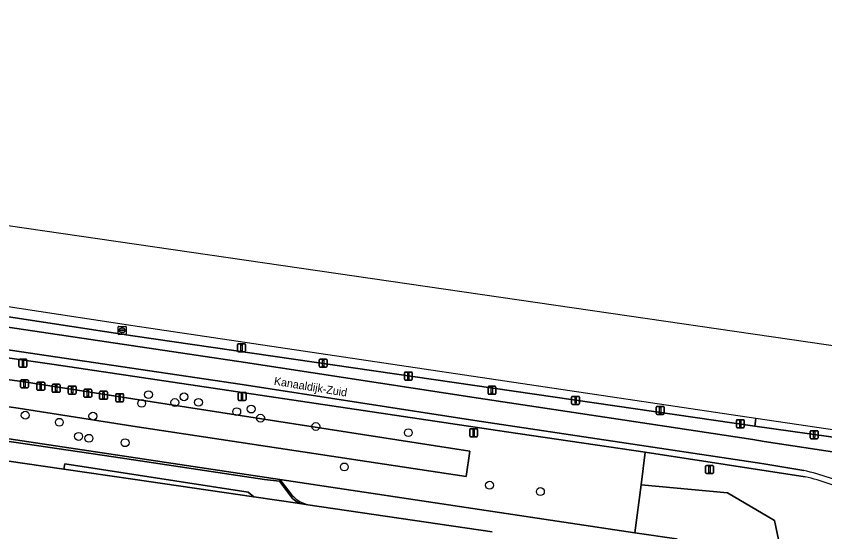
# Model space of a CAD drawing. Extents: x 163043 to 165076, y 382019 to 382874.
# Drawn here: x 164485.4 to 164586.4, y 382621.4 to 382685.8 of the extents above; entities that cross this region are included whole.
import ezdxf

# ---------------------------------------------------------------- set-up
doc = ezdxf.new("R2010")
doc.units = 0
for name, color, linetype in [('IMGEO_Afsluitpaal', 7, 'Continuous'), ('IMGEO_Boom', 7, 'Continuous'), ('IMGEO_Fietspad_gesloten', 7, 'Continuous'), ('IMGEO_Groenvoorziening', 7, 'Continuous'), ('IMGEO_Hek', 7, 'Continuous'), ('IMGEO_Lichtmast', 7, 'Continuous'), ('IMGEO_Loofbos', 7, 'Continuous'), ('IMGEO_Oever', 7, 'Continuous'), ('IMGEO_Openbare_ruimte_label', 7, 'Continuous'), ('IMGEO_Rijbaan_lokaal_gesloten', 7, 'Continuous'), ('IMGEO_Rijbaan_lokaal_halfverhard', 7, 'Continuous'), ('IMGEO_Rioolput', 7, 'Continuous'), ('IMGEO_Waterloop', 7, 'Continuous')]:
    doc.layers.add(name, color=color, linetype=linetype)

msp = doc.modelspace()

# ---------------------------------------------------------------- linework, layer by layer
at = {"layer": 'IMGEO_Afsluitpaal'}
for p, q in [((164513.06, 382643.99), (164513.06, 382644.79)), ((164513.06, 382644.79), (164513.06, 382643.99)), ((164513.16, 382644.89), (164513.95, 382644.89)), ((164513.95, 382644.89), (164513.16, 382644.89)), ((164514.05, 382644.79), (164514.05, 382643.99)), ((164514.05, 382643.99), (164514.05, 382644.79)), ((164513.95, 382643.89), (164513.16, 382643.89)), ((164513.16, 382643.89), (164513.95, 382643.89)), ((164523.25, 382642.07), (164523.25, 382642.87)), ((164523.25, 382642.87), (164523.25, 382642.07)), ((164523.35, 382642.97), (164524.14, 382642.97)), ((164524.14, 382642.97), (164523.35, 382642.97)), ((164524.24, 382642.87), (164524.24, 382642.07)), ((164524.24, 382642.07), (164524.24, 382642.87)), ((164524.14, 382641.97), (164523.35, 382641.97)), ((164523.35, 382641.97), (164524.14, 382641.97)), ((164533.89, 382640.45), (164533.89, 382641.25)), ((164533.89, 382641.25), (164533.89, 382640.45)), ((164533.99, 382641.35), (164534.78, 382641.35)), ((164534.78, 382641.35), (164533.99, 382641.35)), ((164534.88, 382641.25), (164534.88, 382640.45)), ((164534.88, 382640.45), (164534.88, 382641.25)), ((164485.96, 382639.49), (164485.96, 382640.29)), ((164485.96, 382640.29), (164485.96, 382639.49)), ((164486.06, 382640.39), (164486.85, 382640.39)), ((164486.85, 382640.39), (164486.06, 382640.39)), ((164486.95, 382640.29), (164486.95, 382639.49)), ((164486.95, 382639.49), (164486.95, 382640.29)), ((164534.78, 382640.35), (164533.99, 382640.35)), ((164533.99, 382640.35), (164534.78, 382640.35)), ((164486.85, 382639.39), (164486.06, 382639.39)), ((164486.06, 382639.39), (164486.85, 382639.39)), ((164487.99, 382639.19), (164487.99, 382639.99)), ((164487.99, 382639.99), (164487.99, 382639.19)), ((164488.09, 382640.09), (164488.88, 382640.09)), ((164488.88, 382640.09), (164488.09, 382640.09)), ((164488.88, 382639.09), (164488.09, 382639.09)), ((164488.09, 382639.09), (164488.88, 382639.09)), ((164488.98, 382639.99), (164488.98, 382639.19)), ((164488.98, 382639.19), (164488.98, 382639.99)), ((164489.91, 382638.93), (164489.91, 382639.73)), ((164489.91, 382639.73), (164489.91, 382638.93)), ((164490.01, 382639.83), (164490.8, 382639.83)), ((164490.8, 382639.83), (164490.01, 382639.83)), ((164490.9, 382639.73), (164490.9, 382638.93)), ((164490.9, 382638.93), (164490.9, 382639.73)), ((164491.91, 382638.71), (164491.91, 382639.51)), ((164491.91, 382639.51), (164491.91, 382638.71)), ((164492.01, 382639.61), (164492.8, 382639.61)), ((164492.8, 382639.61), (164492.01, 382639.61)), ((164492.9, 382639.51), (164492.9, 382638.71)), ((164492.9, 382638.71), (164492.9, 382639.51)), ((164493.86, 382638.31), (164493.86, 382639.11)), ((164493.86, 382639.11), (164493.86, 382638.31)), ((164493.96, 382639.21), (164494.75, 382639.21)), ((164494.75, 382639.21), (164493.96, 382639.21)), ((164494.85, 382639.11), (164494.85, 382638.31)), ((164494.85, 382638.31), (164494.85, 382639.11)), ((164544.34, 382638.68), (164544.34, 382639.48)), ((164544.34, 382639.48), (164544.34, 382638.68)), ((164544.44, 382639.58), (164545.22, 382639.58)), ((164545.22, 382639.58), (164544.44, 382639.58)), ((164545.32, 382639.48), (164545.32, 382638.68)), ((164545.32, 382638.68), (164545.32, 382639.48)), ((164490.8, 382638.83), (164490.01, 382638.83)), ((164490.01, 382638.83), (164490.8, 382638.83)), ((164492.8, 382638.61), (164492.01, 382638.61)), ((164492.01, 382638.61), (164492.8, 382638.61)), ((164494.75, 382638.21), (164493.96, 382638.21)), ((164493.96, 382638.21), (164494.75, 382638.21)), ((164495.82, 382638.05), (164495.82, 382638.85)), ((164495.82, 382638.85), (164495.82, 382638.05)), ((164495.92, 382638.95), (164496.71, 382638.95)), ((164496.71, 382638.95), (164495.92, 382638.95)), ((164496.81, 382638.85), (164496.81, 382638.05)), ((164496.81, 382638.05), (164496.81, 382638.85)), ((164497.85, 382637.75), (164497.85, 382638.55)), ((164497.85, 382638.55), (164497.85, 382637.75)), ((164497.95, 382638.65), (164498.74, 382638.65)), ((164498.74, 382638.65), (164497.95, 382638.65)), ((164498.84, 382638.55), (164498.84, 382637.75)), ((164498.84, 382637.75), (164498.84, 382638.55)), ((164545.22, 382638.58), (164544.44, 382638.58)), ((164544.44, 382638.58), (164545.22, 382638.58)), ((164554.78, 382637.42), (164554.78, 382638.22)), ((164554.78, 382638.22), (164554.78, 382637.42)), ((164554.88, 382638.32), (164555.67, 382638.32)), ((164555.67, 382638.32), (164554.88, 382638.32)), ((164555.77, 382638.22), (164555.77, 382637.42)), ((164555.77, 382637.42), (164555.77, 382638.22)), ((164496.71, 382637.95), (164495.92, 382637.95)), ((164495.92, 382637.95), (164496.71, 382637.95)), ((164498.74, 382637.65), (164497.95, 382637.65)), ((164497.95, 382637.65), (164498.74, 382637.65)), ((164555.67, 382637.32), (164554.88, 382637.32)), ((164554.88, 382637.32), (164555.67, 382637.32)), ((164565.34, 382636.17), (164565.34, 382636.96)), ((164565.34, 382636.96), (164565.34, 382636.17)), ((164565.44, 382637.06), (164566.23, 382637.06)), ((164566.23, 382637.06), (164565.44, 382637.06)), ((164566.23, 382636.07), (164565.44, 382636.07)), ((164565.44, 382636.07), (164566.23, 382636.07)), ((164566.33, 382636.96), (164566.33, 382636.17)), ((164566.33, 382636.17), (164566.33, 382636.96)), ((164575.35, 382634.5), (164575.35, 382635.3)), ((164575.35, 382635.3), (164575.35, 382634.5)), ((164575.45, 382635.4), (164576.24, 382635.4)), ((164576.24, 382635.4), (164575.45, 382635.4)), ((164576.34, 382635.3), (164576.34, 382634.5)), ((164576.34, 382634.5), (164576.34, 382635.3)), ((164576.24, 382634.4), (164575.45, 382634.4)), ((164575.45, 382634.4), (164576.24, 382634.4)), ((164584.56, 382633.13), (164584.56, 382633.93)), ((164584.56, 382633.93), (164584.56, 382633.13)), ((164584.66, 382634.03), (164585.45, 382634.03)), ((164585.45, 382634.03), (164584.66, 382634.03)), ((164585.45, 382633.03), (164584.66, 382633.03)), ((164584.66, 382633.03), (164585.45, 382633.03)), ((164585.55, 382633.93), (164585.55, 382633.13)), ((164585.55, 382633.13), (164585.55, 382633.93))]:
    msp.add_line(p, q, dxfattribs=at)
for points in [[(164513.48, 382644.77), (164513.63, 382644.77), (164513.63, 382644.02), (164513.48, 382644.02), (164513.48, 382644.77)], [(164523.67, 382642.85), (164523.82, 382642.85), (164523.82, 382642.1), (164523.67, 382642.1), (164523.67, 382642.85)], [(164534.31, 382641.22), (164534.46, 382641.22), (164534.46, 382640.47), (164534.31, 382640.47), (164534.31, 382641.22)], [(164486.38, 382640.26), (164486.53, 382640.26), (164486.53, 382639.51), (164486.38, 382639.51), (164486.38, 382640.26)], [(164488.41, 382639.97), (164488.56, 382639.97), (164488.56, 382639.22), (164488.41, 382639.22), (164488.41, 382639.97)], [(164490.33, 382639.71), (164490.48, 382639.71), (164490.48, 382638.96), (164490.33, 382638.96), (164490.33, 382639.71)], [(164492.33, 382639.49), (164492.48, 382639.49), (164492.48, 382638.74), (164492.33, 382638.74), (164492.33, 382639.49)], [(164544.75, 382639.45), (164544.9, 382639.45), (164544.9, 382638.7), (164544.75, 382638.7), (164544.75, 382639.45)], [(164494.28, 382639.08), (164494.43, 382639.08), (164494.43, 382638.33), (164494.28, 382638.33), (164494.28, 382639.08)], [(164496.24, 382638.82), (164496.39, 382638.82), (164496.39, 382638.07), (164496.24, 382638.07), (164496.24, 382638.82)], [(164498.27, 382638.53), (164498.42, 382638.53), (164498.42, 382637.78), (164498.27, 382637.78), (164498.27, 382638.53)], [(164555.2, 382638.2), (164555.35, 382638.2), (164555.35, 382637.45), (164555.2, 382637.45), (164555.2, 382638.2)], [(164565.76, 382636.94), (164565.91, 382636.94), (164565.91, 382636.19), (164565.76, 382636.19), (164565.76, 382636.94)], [(164575.77, 382635.28), (164575.92, 382635.28), (164575.92, 382634.53), (164575.77, 382634.53), (164575.77, 382635.28)], [(164584.98, 382633.91), (164585.13, 382633.91), (164585.13, 382633.16), (164584.98, 382633.16), (164584.98, 382633.91)]]:
    msp.add_lwpolyline(points, dxfattribs=at)
for centre, start, end in [((164513.16, 382644.79), 90, 180), ((164513.16, 382644.79), 90, 180), ((164513.95, 382644.79), 0, 90), ((164513.95, 382644.79), 360, 90), ((164513.16, 382643.99), 180, 270), ((164513.16, 382643.99), 180, 270), ((164513.95, 382643.99), 270, 0), ((164513.95, 382643.99), 270, 0), ((164523.35, 382642.87), 90, 180), ((164523.35, 382642.87), 90, 180), ((164524.14, 382642.87), 0, 90), ((164524.14, 382642.87), 360, 90), ((164523.35, 382642.07), 180, 270), ((164523.35, 382642.07), 180, 270), ((164524.14, 382642.07), 270, 0), ((164524.14, 382642.07), 270, 0), ((164533.99, 382641.25), 90, 180), ((164533.99, 382641.25), 90, 180), ((164534.78, 382641.25), 0, 90), ((164534.78, 382641.25), 360, 90), ((164486.06, 382640.29), 90, 180), ((164486.06, 382640.29), 90, 180), ((164486.85, 382640.29), 0, 90), ((164486.85, 382640.29), 360, 90), ((164533.99, 382640.45), 180, 270), ((164533.99, 382640.45), 180, 270), ((164534.78, 382640.45), 270, 0), ((164534.78, 382640.45), 270, 0), ((164486.06, 382639.49), 180, 270), ((164486.06, 382639.49), 180, 270), ((164486.85, 382639.49), 270, 0), ((164486.85, 382639.49), 270, 0), ((164488.09, 382639.99), 90, 180), ((164488.09, 382639.99), 90, 180), ((164488.09, 382639.19), 180, 270), ((164488.09, 382639.19), 180, 270), ((164488.88, 382639.99), 0, 90), ((164488.88, 382639.99), 360, 90), ((164488.88, 382639.19), 270, 0), ((164488.88, 382639.19), 270, 0), ((164490.01, 382639.73), 90, 180), ((164490.01, 382639.73), 90, 180), ((164490.8, 382639.73), 0, 90), ((164490.8, 382639.73), 360, 90), ((164492.01, 382639.51), 90, 180), ((164492.01, 382639.51), 90, 180), ((164492.8, 382639.51), 0, 90), ((164492.8, 382639.51), 360, 90), ((164493.96, 382639.11), 90, 180), ((164493.96, 382639.11), 90, 180), ((164494.75, 382639.11), 0, 90), ((164494.75, 382639.11), 360, 90), ((164544.44, 382639.48), 90, 180), ((164544.44, 382639.48), 90, 180), ((164545.22, 382639.48), 0, 90), ((164545.22, 382639.48), 360, 90), ((164490.01, 382638.93), 180, 270), ((164490.01, 382638.93), 180, 270), ((164490.8, 382638.93), 270, 0), ((164490.8, 382638.93), 270, 0), ((164492.01, 382638.71), 180, 270), ((164492.01, 382638.71), 180, 270), ((164492.8, 382638.71), 270, 0), ((164492.8, 382638.71), 270, 0), ((164493.96, 382638.31), 180, 270), ((164493.96, 382638.31), 180, 270), ((164494.75, 382638.31), 270, 0), ((164494.75, 382638.31), 270, 0), ((164495.92, 382638.85), 90, 180), ((164495.92, 382638.85), 90, 180), ((164496.71, 382638.85), 0, 90), ((164496.71, 382638.85), 360, 90), ((164497.95, 382638.55), 90, 180), ((164497.95, 382638.55), 90, 180), ((164498.74, 382638.55), 0, 90), ((164498.74, 382638.55), 360, 90), ((164544.44, 382638.68), 180, 270), ((164544.44, 382638.68), 180, 270), ((164545.22, 382638.68), 270, 0), ((164545.22, 382638.68), 270, 0), ((164554.88, 382638.22), 90, 180), ((164554.88, 382638.22), 90, 180), ((164555.67, 382638.22), 0, 90), ((164555.67, 382638.22), 360, 90), ((164495.92, 382638.05), 180, 270), ((164495.92, 382638.05), 180, 270), ((164496.71, 382638.05), 270, 0), ((164496.71, 382638.05), 270, 0), ((164497.95, 382637.75), 180, 270), ((164497.95, 382637.75), 180, 270), ((164498.74, 382637.75), 270, 0), ((164498.74, 382637.75), 270, 0), ((164554.88, 382637.42), 180, 270), ((164554.88, 382637.42), 180, 270), ((164555.67, 382637.42), 270, 0), ((164555.67, 382637.42), 270, 0), ((164565.44, 382636.96), 90, 180), ((164565.44, 382636.96), 90, 180), ((164565.44, 382636.17), 180, 270), ((164565.44, 382636.17), 180, 270), ((164566.23, 382636.96), 0, 90), ((164566.23, 382636.96), 360, 90), ((164566.23, 382636.17), 270, 0), ((164566.23, 382636.17), 270, 0), ((164575.45, 382635.3), 90, 180), ((164575.45, 382635.3), 90, 180), ((164576.24, 382635.3), 0, 90), ((164576.24, 382635.3), 360, 90), ((164575.45, 382634.5), 180, 270), ((164575.45, 382634.5), 180, 270), ((164576.24, 382634.5), 270, 0), ((164576.24, 382634.5), 270, 0), ((164584.66, 382633.93), 90, 180), ((164584.66, 382633.93), 90, 180), ((164584.66, 382633.13), 180, 270), ((164584.66, 382633.13), 180, 270), ((164585.45, 382633.93), 0, 90), ((164585.45, 382633.93), 360, 90), ((164585.45, 382633.13), 270, 0), ((164585.45, 382633.13), 270, 0)]:
    msp.add_arc(centre, 0.1, start, end, dxfattribs=at)
at = {"layer": 'IMGEO_Boom'}
for centre in [(164501.95, 382638.53), (164506.38, 382638.26), (164501.09, 382637.44), (164505.23, 382637.55), (164508.19, 382637.57), (164514.77, 382636.73), (164486.55, 382635.96), (164495, 382635.84), (164512.96, 382636.4), (164515.93, 382635.6), (164490.81, 382635.08), (164522.84, 382634.55), (164534.39, 382633.78), (164493.21, 382633.31), (164494.5, 382633.08), (164499.02, 382632.52), (164526.39, 382629.5), (164544.53, 382627.21), (164550.88, 382626.42)]:
    msp.add_circle(centre, 0.489, dxfattribs=at)
at = {"layer": 'IMGEO_Fietspad_gesloten'}
for points in [[(164590.1, 382630.98), (164578.83, 382632.68), (164577.4, 382632.94), (164564.45, 382634.88), (164543.13, 382638.08), (164514.06, 382642.55), (164454.95, 382651.33), (164396.3, 382660.19), (164284.35, 382677.28), (164278.14, 382678.22), (164235.35, 382684.54)], [(164283.96, 382674.5), (164395.88, 382657.42), (164454.54, 382648.56), (164513.64, 382639.78), (164542.71, 382635.32), (164564.09, 382632.1), (164578.55, 382629.91), (164583.76, 382629.04)], [(164290.79, 382659.6), (164472.55, 382632.41), (164472.49, 382631.88), (164484.23, 382630.28), (164491.39, 382629.23), (164491.49, 382629.87), (164514.38, 382626.36), (164515.1, 382625.77), (164520.86, 382624.93), (164520.36, 382625.22), (164519.94, 382625.56), (164518.31, 382627.71), (164516.44, 382627.92), (164497.58, 382630.74), (164458.77, 382636.45), (164437.76, 382639.63), (164406.03, 382644.41), (164348.55, 382652.85), (164290.62, 382661.73)]]:
    msp.add_lwpolyline(points, dxfattribs=at)
msp.add_arc((164577.89, 382602.23), 27.45, 63.6861, 77.6519, dxfattribs=at)
at = {"layer": 'IMGEO_Groenvoorziening'}
for points in [[(164619.1, 382628.48), (164619.49, 382628.72), (164577.64, 382634.59), (164500, 382645.86), (164326.61, 382672.42), (164284.55, 382678.7), (164223.39, 382687.83), (164004.16, 382721.06), (164000, 382721.52), (163996.62, 382722), (163984.14, 382724.05), (163984.26, 382724.67), (163957.08, 382728.48), (163893.44, 382737.78)], [(164284.35, 382677.28), (164396.3, 382660.19), (164454.95, 382651.33), (164514.06, 382642.55), (164543.13, 382638.08), (164564.45, 382634.88), (164577.4, 382632.94), (164578.83, 382632.68), (164590.1, 382630.98)], [(164282.56, 382663.33), (164518.36, 382627.93), (164562.67, 382621.28), (164563.46, 382627.27), (164563.98, 382631.34), (164546.63, 382633.89), (164490.17, 382642.3), (164454.45, 382647.37), (164396.2, 382656.23), (164325.74, 382667.17)], [(164519.63, 382626.25), (164518.36, 382627.93), (164282.56, 382663.33)], [(164290.62, 382661.73), (164348.55, 382652.85), (164406.03, 382644.41), (164437.76, 382639.63), (164458.77, 382636.45), (164497.58, 382630.74), (164516.44, 382627.92), (164518.31, 382627.71), (164519.94, 382625.56), (164520.36, 382625.22), (164520.86, 382624.93), (164521.84, 382624.78)], [(164583.94, 382628.28), (164563.98, 382631.34), (164563.46, 382627.27), (164574.24, 382626.25), (164580.11, 382622.82), (164581.1, 382618.05), (164578.56, 382613.96), (164573.96, 382611.95), (164640.91, 382517.91), (164661.85, 382488.63), (164685.89, 382499.46), (164694.96, 382503.59), (164744.78, 382526.26), (164740.74, 382535.71)], [(164688.62, 382460.91), (164694.96, 382503.59), (164685.89, 382499.46), (164661.85, 382488.63), (164640.91, 382517.91), (164573.96, 382611.95), (164567.87, 382620.5), (164562.67, 382621.28), (164518.36, 382627.93), (164519.63, 382626.25)], [(164521.84, 382624.78), (164544.84, 382621.39)]]:
    msp.add_lwpolyline(points, dxfattribs=at)
for points in [[(164229.4, 382676.95), (164337.68, 382660.69), (164416.83, 382649.81), (164431.81, 382647.48), (164450.46, 382644.94), (164486.15, 382640.16), (164500, 382638.01), (164542.07, 382631.47), (164541.63, 382628.3), (164500, 382634.6), (164485.67, 382636.85), (164404.8, 382648.54), (164314.83, 382661.08), (164228.97, 382674.04)], [(164491.39, 382629.23), (164500, 382627.97), (164515.1, 382625.77), (164514.38, 382626.36), (164491.49, 382629.87)]]:
    msp.add_lwpolyline(points, close=True, dxfattribs=at)
for centre, radius, start, end in [((164576.73, 382597.84), 31.28, 65.2088, 76.6616), ((164522.82, 382628.66), 4, 217.0042, 255.7236), ((164522.82, 382628.66), 4, 217.0042, 255.7236)]:
    msp.add_arc(centre, radius, start, end, dxfattribs=at)
at = {"layer": 'IMGEO_Hek'}
for points in [[(164518.36, 382627.93), (164282.56, 382663.33)], [(164562.67, 382621.28), (164518.36, 382627.93)]]:
    msp.add_lwpolyline(points, dxfattribs=at)
at = {"layer": 'IMGEO_Lichtmast'}
for p, q in [((164485.77, 382642.07), (164485.77, 382642.87)), ((164485.77, 382642.87), (164485.77, 382642.07)), ((164485.87, 382642.97), (164486.66, 382642.97)), ((164486.66, 382642.97), (164485.87, 382642.97)), ((164486.76, 382642.87), (164486.76, 382642.07)), ((164486.76, 382642.07), (164486.76, 382642.87)), ((164486.66, 382641.97), (164485.87, 382641.97)), ((164485.87, 382641.97), (164486.66, 382641.97)), ((164513.13, 382637.91), (164513.13, 382638.71)), ((164513.13, 382638.71), (164513.13, 382637.91)), ((164513.23, 382638.81), (164514.02, 382638.81)), ((164514.02, 382638.81), (164513.23, 382638.81)), ((164514.12, 382638.71), (164514.12, 382637.91)), ((164514.12, 382637.91), (164514.12, 382638.71)), ((164514.02, 382637.81), (164513.23, 382637.81)), ((164513.23, 382637.81), (164514.02, 382637.81)), ((164542.05, 382633.37), (164542.05, 382634.17)), ((164542.05, 382634.17), (164542.05, 382633.37)), ((164542.15, 382634.27), (164542.94, 382634.27)), ((164542.94, 382634.27), (164542.15, 382634.27)), ((164543.04, 382634.17), (164543.04, 382633.37)), ((164543.04, 382633.37), (164543.04, 382634.17)), ((164542.94, 382633.27), (164542.15, 382633.27)), ((164542.15, 382633.27), (164542.94, 382633.27)), ((164571.51, 382628.78), (164571.51, 382629.58)), ((164571.51, 382629.58), (164571.51, 382628.78)), ((164571.61, 382629.68), (164572.4, 382629.68)), ((164572.4, 382629.68), (164571.61, 382629.68)), ((164572.5, 382629.58), (164572.5, 382628.78)), ((164572.5, 382628.78), (164572.5, 382629.58)), ((164572.4, 382628.68), (164571.61, 382628.68)), ((164571.61, 382628.68), (164572.4, 382628.68))]:
    msp.add_line(p, q, dxfattribs=at)
for points in [[(164486.19, 382642.85), (164486.34, 382642.85), (164486.34, 382642.1), (164486.19, 382642.1), (164486.19, 382642.85)], [(164513.55, 382638.68), (164513.7, 382638.68), (164513.7, 382637.93), (164513.55, 382637.93), (164513.55, 382638.68)], [(164542.47, 382634.15), (164542.62, 382634.15), (164542.62, 382633.4), (164542.47, 382633.4), (164542.47, 382634.15)], [(164571.93, 382629.56), (164572.08, 382629.56), (164572.08, 382628.81), (164571.93, 382628.81), (164571.93, 382629.56)]]:
    msp.add_lwpolyline(points, dxfattribs=at)
for centre, start, end in [((164485.87, 382642.87), 90, 180), ((164485.87, 382642.87), 90, 180), ((164486.66, 382642.87), 0, 90), ((164486.66, 382642.87), 360, 90), ((164485.87, 382642.07), 180, 270), ((164485.87, 382642.07), 180, 270), ((164486.66, 382642.07), 270, 0), ((164486.66, 382642.07), 270, 0), ((164513.23, 382638.71), 90, 180), ((164513.23, 382638.71), 90, 180), ((164514.02, 382638.71), 0, 90), ((164514.02, 382638.71), 360, 90), ((164513.23, 382637.91), 180, 270), ((164513.23, 382637.91), 180, 270), ((164514.02, 382637.91), 270, 0), ((164514.02, 382637.91), 270, 0), ((164542.15, 382634.17), 90, 180), ((164542.15, 382634.17), 90, 180), ((164542.94, 382634.17), 0, 90), ((164542.94, 382634.17), 360, 90), ((164542.15, 382633.37), 180, 270), ((164542.15, 382633.37), 180, 270), ((164542.94, 382633.37), 270, 0), ((164542.94, 382633.37), 270, 0), ((164571.61, 382629.58), 90, 180), ((164571.61, 382629.58), 90, 180), ((164572.4, 382629.58), 0, 90), ((164572.4, 382629.58), 360, 90), ((164571.61, 382628.78), 180, 270), ((164571.61, 382628.78), 180, 270), ((164572.4, 382628.78), 270, 0), ((164572.4, 382628.78), 270, 0)]:
    msp.add_arc(centre, 0.1, start, end, dxfattribs=at)
at = {"layer": 'IMGEO_Loofbos'}
msp.add_lwpolyline([(164573.96, 382611.95), (164578.56, 382613.96), (164581.1, 382618.05), (164580.11, 382622.82), (164574.24, 382626.25), (164563.46, 382627.27), (164562.67, 382621.28), (164567.87, 382620.5)], close=True, dxfattribs=at)
at = {"layer": 'IMGEO_Oever'}
for points in [[(164390.46, 382663.82), (164301.17, 382677.11), (164284.68, 382679.59), (164284.55, 382678.7), (164326.61, 382672.42), (164500, 382645.86), (164577.64, 382634.59), (164577.79, 382635.57), (164500, 382647.13)], [(164577.79, 382635.57), (164577.64, 382634.59), (164619.49, 382628.72), (164620.09, 382628.61), (164620.89, 382628.51), (164623.42, 382628.16), (164624.27, 382628.05), (164626.88, 382627.58), (164633.2, 382626.7), (164633.68, 382626.68), (164634.83, 382626.12), (164634.2, 382626.66), (164633.6, 382627.18), (164629.53, 382628.14), (164625.1, 382628.81), (164610.23, 382630.74)]]:
    msp.add_lwpolyline(points, close=True, dxfattribs=at)
at = {"layer": 'IMGEO_Rijbaan_lokaal_gesloten'}
msp.add_lwpolyline([(164544.84, 382621.39), (164521.84, 382624.78), (164520.86, 382624.93), (164515.1, 382625.77), (164500, 382627.97), (164491.39, 382629.23), (164484.23, 382630.28), (164472.49, 382631.88), (164467.18, 382632.47), (164458.53, 382633.3), (164451.73, 382634.17), (164290.57, 382658.01)], dxfattribs=at)
at = {"layer": 'IMGEO_Rijbaan_lokaal_halfverhard'}
for points in [[(164583.76, 382629.04), (164578.55, 382629.91), (164564.09, 382632.1), (164542.71, 382635.32), (164513.64, 382639.78), (164454.54, 382648.56), (164395.88, 382657.42), (164283.96, 382674.5), (164277.72, 382675.46), (164234.94, 382681.77), (164226.11, 382682.88), (164210.1, 382685.24), (164199.47, 382687.05), (164086.12, 382704.22), (163983.27, 382719.37), (163935.2, 382726.45), (163865.22, 382736.76), (163777.02, 382749.58)], [(164325.74, 382667.17), (164396.2, 382656.23), (164454.45, 382647.37), (164490.17, 382642.3), (164546.63, 382633.89), (164563.98, 382631.34), (164583.94, 382628.28)]]:
    msp.add_lwpolyline(points, dxfattribs=at)
for centre, radius, start, end in [((164577.89, 382602.23), 27.45, 63.6861, 77.6519), ((164576.73, 382597.84), 31.28, 65.2088, 76.6616)]:
    msp.add_arc(centre, radius, start, end, dxfattribs=at)
at = {"layer": 'IMGEO_Rioolput'}
for p, q in [((164498.15, 382646.14), (164498.15, 382646.99)), ((164498.22, 382647.06), (164499.07, 382647.06)), ((164498.4, 382646.56), (164498.4, 382646.57)), ((164498.84, 382646.52), (164498.44, 382646.52)), ((164498.45, 382646.61), (164498.84, 382646.61)), ((164498.63, 382646.84), (164498.66, 382646.84)), ((164498.66, 382646.28), (164498.63, 382646.28)), ((164498.89, 382646.57), (164498.89, 382646.56)), ((164499.15, 382646.99), (164499.15, 382646.14)), ((164499.07, 382646.06), (164498.22, 382646.06))]:
    msp.add_line(p, q, dxfattribs=at)
for points in [[(164498.15, 382646.14), (164498.15, 382646.99)], [(164498.22, 382647.06), (164499.07, 382647.06)], [(164499.15, 382646.99), (164499.15, 382646.14)], [(164499.07, 382646.06), (164498.22, 382646.06)]]:
    msp.add_lwpolyline(points, dxfattribs=at)
for centre, radius, start, end in [((164498.22, 382646.99), 0.0765, 91.552, 178.448), ((164498.22, 382646.99), 0.0765, 91.552, 178.448), ((164498.44, 382646.57), 0.0403, 85.8775, 175.7526), ((164498.44, 382646.56), 0.0366, 178.938, 274.7102), ((164498.85, 382646.57), 0.0386, 1.7309, 96.639), ((164498.85, 382646.56), 0.043, 264.8664, 352.4533), ((164499.07, 382646.99), 0.0765, 1.552, 88.448), ((164499.07, 382646.99), 0.0765, 1.552, 88.448), ((164498.22, 382646.14), 0.0765, 181.552, 268.448), ((164498.22, 382646.14), 0.0765, 181.552, 268.448), ((164499.07, 382646.14), 0.0765, 271.552, 358.448), ((164499.07, 382646.14), 0.0765, 271.552, 358.448)]:
    msp.add_arc(centre, radius, start, end, dxfattribs=at)
for centre, major_axis, ratio, start_param, end_param in [((164498.63, 382646.56), (-0.387, 0.002), 0.722429, 4.712389, 7.853982), ((164498.66, 382646.56), (-0.39, 0.002), 0.717154, 1.570796, 4.712389)]:
    msp.add_ellipse(centre, major_axis=major_axis, ratio=ratio, start_param=start_param, end_param=end_param, dxfattribs=at)
at = {"layer": 'IMGEO_Waterloop'}
for points in [[(164147.9, 382708.69), (165075.56, 382573.63)], [(164646.15, 382578.67), (164648.15, 382575.86), (164646.82, 382574.91), (164645.66, 382576.54), (164645.01, 382576.01), (164646.01, 382574.6), (164643.89, 382573.15), (164641.83, 382575.7), (164638.88, 382582.41), (164637.27, 382588.62), (164636.11, 382596.73), (164635.78, 382603.55), (164635.36, 382615.73), (164634.83, 382626.11), (164634.83, 382626.12), (164634.2, 382626.66), (164633.6, 382627.18), (164629.53, 382628.14), (164625.1, 382628.81), (164610.23, 382630.74), (164577.79, 382635.57), (164500, 382647.13), (164390.46, 382663.82), (164301.17, 382677.11)]]:
    msp.add_lwpolyline(points, dxfattribs=at)
msp.add_lwpolyline([(164542.07, 382631.47), (164500, 382638.01), (164486.15, 382640.16), (164450.46, 382644.94), (164431.81, 382647.48), (164416.83, 382649.81), (164337.68, 382660.69), (164229.4, 382676.95), (164228.97, 382674.04), (164314.83, 382661.08), (164404.8, 382648.54), (164485.67, 382636.85), (164500, 382634.6), (164541.63, 382628.3)], close=True, dxfattribs=at)

# ---------------------------------------------------------------- texts
at = {"layer": 'IMGEO_Openbare_ruimte_label'}
msp.add_text('Kanaaldijk-Zuid', height=1, rotation=350.6789, dxfattribs=at).set_placement((164517.56, 382639.77))

doc.saveas('drawing.dxf')
